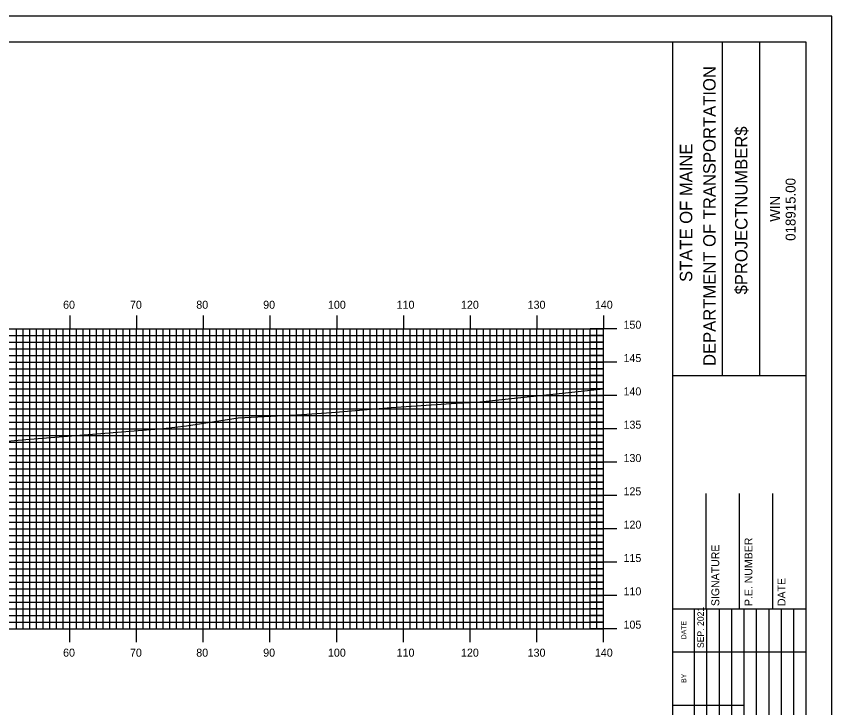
# Model space of a CAD drawing. Extents: x 1782254 to 1782597, y 442591 to 442811.
# Drawn here: x 1782471.4 to 1782593.6, y 442706.8 to 442810.5 of the extents above; entities that cross this region are included whole.
import ezdxf

# ---------------------------------------------------------------- set-up
doc = ezdxf.new("R2010")
doc.units = 0
for name, color, linetype in [('BORDER', 7, 'Continuous'), ('H_V ANNOTATION', 7, 'Continuous'), ('MAJOR', 7, 'Continuous'), ('MINOR', 7, 'Continuous'), ('PLOT BOUNDARY', 7, 'Continuous'), ('S_Roadway_Centerline', 7, 'Continuous')]:
    doc.layers.add(name, color=color, linetype=linetype)

msp = doc.modelspace()

# ---------------------------------------------------------------- linework, layer by layer
at = {"layer": 'BORDER'}
for p, q in [((1782569.83, 442596.67), (1782569.83, 442806.67)), ((1782577.29, 442756.66), (1782577.29, 442806.66)), ((1782582.88, 442756.66), (1782582.88, 442806.66)), ((1782569.84, 442756.65), (1782589.83, 442756.65)), ((1782569.84, 442756.65), (1782589.83, 442756.65)), ((1782574.83, 442721.67), (1782574.83, 442738.97)), ((1782574.83, 442721.67), (1782574.83, 442738.97)), ((1782579.83, 442721.67), (1782579.83, 442738.97)), ((1782579.83, 442721.67), (1782579.83, 442738.97)), ((1782584.83, 442721.67), (1782584.83, 442738.97)), ((1782584.83, 442721.67), (1782584.83, 442738.97)), ((1782569.83, 442721.67), (1782589.83, 442721.67)), ((1782569.83, 442721.67), (1782589.83, 442721.67))]:
    msp.add_line(p, q, dxfattribs=at)
msp.add_lwpolyline([(1782269.83, 442596.67), (1782589.83, 442596.67), (1782589.83, 442806.67), (1782269.83, 442806.67)], close=True, dxfattribs=at)
for points in [[(1782573.06, 442715.17), (1782573.06, 442721.67)], [(1782573.06, 442715.17), (1782573.06, 442721.67)], [(1782574.93, 442686.68), (1782574.93, 442721.67)], [(1782574.93, 442686.68), (1782574.93, 442721.67)], [(1782576.79, 442721.67), (1782576.79, 442686.68)], [(1782576.79, 442721.67), (1782576.79, 442686.68)], [(1782578.66, 442686.68), (1782578.66, 442721.67)], [(1782578.66, 442686.68), (1782578.66, 442721.67)], [(1782580.52, 442686.68), (1782580.52, 442721.67)], [(1782580.52, 442686.68), (1782580.52, 442721.67)], [(1782582.38, 442686.68), (1782582.38, 442721.67)], [(1782582.38, 442686.68), (1782582.38, 442721.67)], [(1782584.25, 442686.68), (1782584.25, 442721.67)], [(1782584.25, 442686.68), (1782584.25, 442721.67)], [(1782586.11, 442686.68), (1782586.11, 442721.67)], [(1782586.11, 442686.68), (1782586.11, 442721.67)], [(1782587.97, 442686.68), (1782587.97, 442721.67)], [(1782587.97, 442686.68), (1782587.97, 442721.67)], [(1782573.07, 442686.68), (1782573.07, 442720.26)], [(1782573.07, 442686.68), (1782573.07, 442720.26)], [(1782569.83, 442715.17), (1782589.83, 442715.17)], [(1782569.83, 442715.17), (1782589.83, 442715.17)], [(1782569.83, 442707.17), (1782573.07, 442707.17)], [(1782569.83, 442707.17), (1782573.07, 442707.17)], [(1782573.06, 442707.17), (1782580.52, 442707.17)], [(1782573.06, 442707.17), (1782580.52, 442707.17)]]:
    msp.add_lwpolyline(points, dxfattribs=at)
at = {"layer": 'MAJOR'}
for p, q in [((1782479.43, 442765.67), (1782479.43, 442763.67)), ((1782489.43, 442765.67), (1782489.43, 442763.67)), ((1782499.43, 442765.67), (1782499.43, 442763.67)), ((1782509.43, 442765.67), (1782509.43, 442763.67)), ((1782519.43, 442765.67), (1782519.43, 442763.67)), ((1782529.43, 442765.67), (1782529.43, 442763.67)), ((1782539.43, 442765.67), (1782539.43, 442763.67)), ((1782549.43, 442765.67), (1782549.43, 442763.67)), ((1782559.43, 442765.67), (1782559.43, 442763.67)), ((1782279.43, 442763.67), (1782559.43, 442763.67)), ((1782279.43, 442763.67), (1782559.43, 442763.67)), ((1782479.43, 442718.67), (1782479.43, 442763.67)), ((1782489.43, 442718.67), (1782489.43, 442763.67)), ((1782499.43, 442718.67), (1782499.43, 442763.67)), ((1782509.43, 442718.67), (1782509.43, 442763.67)), ((1782519.43, 442718.67), (1782519.43, 442763.67)), ((1782529.43, 442718.67), (1782529.43, 442763.67)), ((1782539.43, 442718.67), (1782539.43, 442763.67)), ((1782549.43, 442718.67), (1782549.43, 442763.67)), ((1782561.44, 442763.67), (1782557.43, 442763.67)), ((1782559.43, 442718.67), (1782559.43, 442763.67)), ((1782559.43, 442718.67), (1782559.43, 442763.67)), ((1782279.43, 442758.67), (1782559.43, 442758.67)), ((1782561.44, 442758.67), (1782557.43, 442758.67)), ((1782279.43, 442753.67), (1782559.43, 442753.67)), ((1782561.44, 442753.67), (1782557.43, 442753.67)), ((1782279.43, 442748.67), (1782559.43, 442748.67)), ((1782561.44, 442748.67), (1782557.43, 442748.67)), ((1782279.43, 442743.67), (1782559.43, 442743.67)), ((1782561.44, 442743.67), (1782557.43, 442743.67)), ((1782279.43, 442738.67), (1782559.43, 442738.67)), ((1782561.44, 442738.67), (1782557.43, 442738.67)), ((1782279.43, 442733.67), (1782559.43, 442733.67)), ((1782561.44, 442733.67), (1782557.43, 442733.67)), ((1782279.43, 442728.67), (1782559.43, 442728.67)), ((1782561.44, 442728.67), (1782557.43, 442728.67)), ((1782279.43, 442723.67), (1782559.43, 442723.67)), ((1782561.44, 442723.67), (1782557.43, 442723.67)), ((1782279.43, 442718.67), (1782559.43, 442718.67)), ((1782279.43, 442718.67), (1782559.43, 442718.67)), ((1782479.43, 442716.66), (1782479.43, 442718.67)), ((1782489.43, 442716.66), (1782489.43, 442718.67)), ((1782499.43, 442716.66), (1782499.43, 442718.67)), ((1782509.43, 442716.66), (1782509.43, 442718.67)), ((1782519.43, 442716.66), (1782519.43, 442718.67)), ((1782529.43, 442716.66), (1782529.43, 442718.67)), ((1782539.43, 442716.66), (1782539.43, 442718.67)), ((1782549.43, 442716.66), (1782549.43, 442718.67)), ((1782561.44, 442718.67), (1782557.43, 442718.67)), ((1782559.43, 442716.66), (1782559.43, 442718.67))]:
    msp.add_line(p, q, dxfattribs=at)
at = {"layer": 'MINOR'}
for p, q in [((1782471.43, 442718.67), (1782471.43, 442763.67)), ((1782472.43, 442718.67), (1782472.43, 442763.67)), ((1782473.43, 442718.67), (1782473.43, 442763.67)), ((1782474.43, 442718.67), (1782474.43, 442763.67)), ((1782475.43, 442718.67), (1782475.43, 442763.67)), ((1782476.43, 442718.67), (1782476.43, 442763.67)), ((1782477.43, 442718.67), (1782477.43, 442763.67)), ((1782478.43, 442718.67), (1782478.43, 442763.67)), ((1782480.43, 442718.67), (1782480.43, 442763.67)), ((1782481.43, 442718.67), (1782481.43, 442763.67)), ((1782482.43, 442718.67), (1782482.43, 442763.67)), ((1782483.43, 442718.67), (1782483.43, 442763.67)), ((1782484.43, 442718.67), (1782484.43, 442763.67)), ((1782485.43, 442718.67), (1782485.43, 442763.67)), ((1782486.43, 442718.67), (1782486.43, 442763.67)), ((1782487.43, 442718.67), (1782487.43, 442763.67)), ((1782488.43, 442718.67), (1782488.43, 442763.67)), ((1782490.43, 442718.67), (1782490.43, 442763.67)), ((1782491.43, 442718.67), (1782491.43, 442763.67)), ((1782492.43, 442718.67), (1782492.43, 442763.67)), ((1782493.43, 442718.67), (1782493.43, 442763.67)), ((1782494.43, 442718.67), (1782494.43, 442763.67)), ((1782495.43, 442718.67), (1782495.43, 442763.67)), ((1782496.43, 442718.67), (1782496.43, 442763.67)), ((1782497.43, 442718.67), (1782497.43, 442763.67)), ((1782498.43, 442718.67), (1782498.43, 442763.67)), ((1782500.43, 442718.67), (1782500.43, 442763.67)), ((1782501.43, 442718.67), (1782501.43, 442763.67)), ((1782502.43, 442718.67), (1782502.43, 442763.67)), ((1782503.43, 442718.67), (1782503.43, 442763.67)), ((1782504.43, 442718.67), (1782504.43, 442763.67)), ((1782505.43, 442718.67), (1782505.43, 442763.67)), ((1782506.43, 442718.67), (1782506.43, 442763.67)), ((1782507.43, 442718.67), (1782507.43, 442763.67)), ((1782508.43, 442718.67), (1782508.43, 442763.67)), ((1782510.43, 442718.67), (1782510.43, 442763.67)), ((1782511.43, 442718.67), (1782511.43, 442763.67)), ((1782512.43, 442718.67), (1782512.43, 442763.67)), ((1782513.43, 442718.67), (1782513.43, 442763.67)), ((1782514.43, 442718.67), (1782514.43, 442763.67)), ((1782515.43, 442718.67), (1782515.43, 442763.67)), ((1782516.43, 442718.67), (1782516.43, 442763.67)), ((1782517.43, 442718.67), (1782517.43, 442763.67)), ((1782518.43, 442718.67), (1782518.43, 442763.67)), ((1782520.43, 442718.67), (1782520.43, 442763.67)), ((1782521.43, 442718.67), (1782521.43, 442763.67)), ((1782522.43, 442718.67), (1782522.43, 442763.67)), ((1782523.43, 442718.67), (1782523.43, 442763.67)), ((1782524.43, 442718.67), (1782524.43, 442763.67)), ((1782525.43, 442718.67), (1782525.43, 442763.67)), ((1782526.43, 442718.67), (1782526.43, 442763.67)), ((1782527.43, 442718.67), (1782527.43, 442763.67)), ((1782528.43, 442718.67), (1782528.43, 442763.67)), ((1782530.43, 442718.67), (1782530.43, 442763.67)), ((1782531.43, 442718.67), (1782531.43, 442763.67)), ((1782532.43, 442718.67), (1782532.43, 442763.67)), ((1782533.43, 442718.67), (1782533.43, 442763.67)), ((1782534.43, 442718.67), (1782534.43, 442763.67)), ((1782535.43, 442718.67), (1782535.43, 442763.67)), ((1782536.43, 442718.67), (1782536.43, 442763.67)), ((1782537.43, 442718.67), (1782537.43, 442763.67)), ((1782538.43, 442718.67), (1782538.43, 442763.67)), ((1782540.43, 442718.67), (1782540.43, 442763.67)), ((1782541.43, 442718.67), (1782541.43, 442763.67)), ((1782542.43, 442718.67), (1782542.43, 442763.67)), ((1782543.43, 442718.67), (1782543.43, 442763.67)), ((1782544.43, 442718.67), (1782544.43, 442763.67)), ((1782545.43, 442718.67), (1782545.43, 442763.67)), ((1782546.43, 442718.67), (1782546.43, 442763.67)), ((1782547.43, 442718.67), (1782547.43, 442763.67)), ((1782548.43, 442718.67), (1782548.43, 442763.67)), ((1782550.43, 442718.67), (1782550.43, 442763.67)), ((1782551.43, 442718.67), (1782551.43, 442763.67)), ((1782552.43, 442718.67), (1782552.43, 442763.67)), ((1782553.43, 442718.67), (1782553.43, 442763.67)), ((1782554.43, 442718.67), (1782554.43, 442763.67)), ((1782555.43, 442718.67), (1782555.43, 442763.67)), ((1782556.43, 442718.67), (1782556.43, 442763.67)), ((1782557.43, 442718.67), (1782557.43, 442763.67)), ((1782558.43, 442718.67), (1782558.43, 442763.67)), ((1782279.43, 442762.67), (1782559.43, 442762.67)), ((1782279.43, 442761.67), (1782559.43, 442761.67)), ((1782559.43, 442762.67), (1782557.43, 442762.67)), ((1782559.43, 442761.67), (1782557.43, 442761.67)), ((1782279.43, 442760.67), (1782559.43, 442760.67)), ((1782559.43, 442760.67), (1782557.43, 442760.67)), ((1782279.43, 442759.67), (1782559.43, 442759.67)), ((1782559.43, 442759.67), (1782557.43, 442759.67)), ((1782279.43, 442757.67), (1782559.43, 442757.67)), ((1782279.43, 442756.67), (1782559.43, 442756.67)), ((1782559.43, 442757.67), (1782557.43, 442757.67)), ((1782559.43, 442756.67), (1782557.43, 442756.67)), ((1782279.43, 442755.67), (1782559.43, 442755.67)), ((1782559.43, 442755.67), (1782557.43, 442755.67)), ((1782279.43, 442754.67), (1782559.43, 442754.67)), ((1782559.43, 442754.67), (1782557.43, 442754.67)), ((1782279.43, 442752.67), (1782559.43, 442752.67)), ((1782559.43, 442752.67), (1782557.43, 442752.67)), ((1782279.43, 442751.67), (1782559.43, 442751.67)), ((1782279.43, 442750.67), (1782559.43, 442750.67)), ((1782559.43, 442751.67), (1782557.43, 442751.67)), ((1782559.43, 442750.67), (1782557.43, 442750.67)), ((1782279.43, 442749.67), (1782559.43, 442749.67)), ((1782559.43, 442749.67), (1782557.43, 442749.67)), ((1782279.43, 442747.67), (1782559.43, 442747.67)), ((1782559.43, 442747.67), (1782557.43, 442747.67)), ((1782279.43, 442746.67), (1782559.43, 442746.67)), ((1782279.43, 442745.67), (1782559.43, 442745.67)), ((1782559.43, 442746.67), (1782557.43, 442746.67)), ((1782559.43, 442745.67), (1782557.43, 442745.67)), ((1782279.43, 442744.67), (1782559.43, 442744.67)), ((1782559.43, 442744.67), (1782557.43, 442744.67)), ((1782279.43, 442742.67), (1782559.43, 442742.67)), ((1782559.43, 442742.67), (1782557.43, 442742.67)), ((1782279.43, 442741.67), (1782559.43, 442741.67)), ((1782559.43, 442741.67), (1782557.43, 442741.67)), ((1782279.43, 442740.67), (1782559.43, 442740.67)), ((1782279.43, 442739.67), (1782559.43, 442739.67)), ((1782559.43, 442740.67), (1782557.43, 442740.67)), ((1782559.43, 442739.67), (1782557.43, 442739.67)), ((1782279.43, 442737.67), (1782559.43, 442737.67)), ((1782559.43, 442737.67), (1782557.43, 442737.67)), ((1782279.43, 442736.67), (1782559.43, 442736.67)), ((1782559.43, 442736.67), (1782557.43, 442736.67)), ((1782279.43, 442735.67), (1782559.43, 442735.67)), ((1782279.43, 442734.67), (1782559.43, 442734.67)), ((1782559.43, 442735.67), (1782557.43, 442735.67)), ((1782559.43, 442734.67), (1782557.43, 442734.67)), ((1782279.43, 442732.67), (1782559.43, 442732.67)), ((1782559.43, 442732.67), (1782557.43, 442732.67)), ((1782279.43, 442731.67), (1782559.43, 442731.67)), ((1782559.43, 442731.67), (1782557.43, 442731.67)), ((1782279.43, 442730.67), (1782559.43, 442730.67)), ((1782559.43, 442730.67), (1782557.43, 442730.67)), ((1782279.43, 442729.67), (1782559.43, 442729.67)), ((1782559.43, 442729.67), (1782557.43, 442729.67)), ((1782279.43, 442727.67), (1782559.43, 442727.67)), ((1782559.43, 442727.67), (1782557.43, 442727.67)), ((1782279.43, 442726.67), (1782559.43, 442726.67)), ((1782559.43, 442726.67), (1782557.43, 442726.67)), ((1782279.43, 442725.67), (1782559.43, 442725.67)), ((1782559.43, 442725.67), (1782557.43, 442725.67)), ((1782279.43, 442724.67), (1782559.43, 442724.67)), ((1782559.43, 442724.67), (1782557.43, 442724.67)), ((1782279.43, 442722.67), (1782559.43, 442722.67)), ((1782559.43, 442722.67), (1782557.43, 442722.67)), ((1782279.43, 442721.67), (1782559.43, 442721.67)), ((1782559.43, 442721.67), (1782557.43, 442721.67)), ((1782279.43, 442720.67), (1782559.43, 442720.67)), ((1782559.43, 442720.67), (1782557.43, 442720.67)), ((1782279.43, 442719.67), (1782559.43, 442719.67)), ((1782559.43, 442719.67), (1782557.43, 442719.67))]:
    msp.add_line(p, q, dxfattribs=at)
at = {"layer": 'PLOT BOUNDARY'}
msp.add_lwpolyline([(1782253.65, 442590.55), (1782593.65, 442590.55), (1782593.65, 442810.55), (1782253.65, 442810.55)], close=True, dxfattribs=at)
at = {"layer": 'S_Roadway_Centerline'}
msp.add_lwpolyline([(1782469.44, 442746.74), (1782472.85, 442747.04), (1782493.4, 442748.7), (1782496.9, 442749.11), (1782504.64, 442750.29), (1782513.48, 442750.77), (1782518.67, 442751.1), (1782527.62, 442751.83), (1782537.33, 442752.49), (1782540.38, 442752.67), (1782559.43, 442754.63)], dxfattribs=at)

# ---------------------------------------------------------------- texts
at = {"layer": 'BORDER'}
for s, height, p in [('DEPARTMENT OF TRANSPORTATION', 1.8635, (1782576.25, 442758.08)), ('$PROJECTNUMBER$', 1.8635, (1782581.02, 442768.82)), ('$PROJECTNUMBER$', 1.8635, (1782581.02, 442768.82)), ('STATE OF MAINE', 1.8635, (1782572.74, 442770.69)), ('018915.00', 1.491, (1782588.23, 442776.86)), ('WIN', 1.491, (1782585.91, 442779.73)), ('WIN', 1.491, (1782585.91, 442779.73)), ('P.E. NUMBER', 1.1811, (1782581.76, 442722.06)), ('P.E. NUMBER', 1.1811, (1782581.76, 442722.06)), ('SIGNATURE', 1.181, (1782576.79, 442722.06)), ('SIGNATURE', 1.181, (1782576.79, 442722.06)), ('DATE', 1.181, (1782586.72, 442722.06)), ('DATE', 1.181, (1782586.72, 442722.06)), ('SEP. 2021', 0.969, (1782574.48, 442715.76)), ('DATE', 0.743, (1782571.84, 442717.08)), ('DATE', 0.743, (1782571.84, 442717.08)), ('BY', 0.743, (1782571.84, 442710.54)), ('BY', 0.743, (1782571.84, 442710.54))]:
    msp.add_text(s, height=height, rotation=90, dxfattribs=at).set_placement(p)
at = {"layer": 'H_V ANNOTATION'}
for s, p in [('60', (1782478.41, 442766.67)), ('70', (1782488.44, 442766.67)), ('80', (1782498.38, 442766.67)), ('90', (1782508.41, 442766.67)), ('100', (1782518.12, 442766.67)), ('110', (1782528.42, 442766.67)), ('120', (1782538.07, 442766.67)), ('130', (1782548.06, 442766.67)), ('140', (1782558.14, 442766.67)), ('150', (1782562.43, 442763.67)), ('145', (1782562.43, 442758.67)), ('140', (1782562.43, 442753.67)), ('135', (1782562.43, 442748.67)), ('130', (1782562.43, 442743.67)), ('125', (1782562.43, 442738.67)), ('120', (1782562.43, 442733.67)), ('115', (1782562.43, 442728.67)), ('110', (1782562.43, 442723.67)), ('105', (1782562.43, 442718.67)), ('60', (1782478.41, 442714.47)), ('70', (1782488.44, 442714.47)), ('80', (1782498.38, 442714.47)), ('90', (1782508.41, 442714.47)), ('100', (1782518.12, 442714.47)), ('110', (1782528.42, 442714.47)), ('120', (1782538.07, 442714.47)), ('130', (1782548.06, 442714.47)), ('140', (1782558.14, 442714.47))]:
    msp.add_text(s, height=1.2, dxfattribs=at).set_placement(p)

doc.saveas('drawing.dxf')
